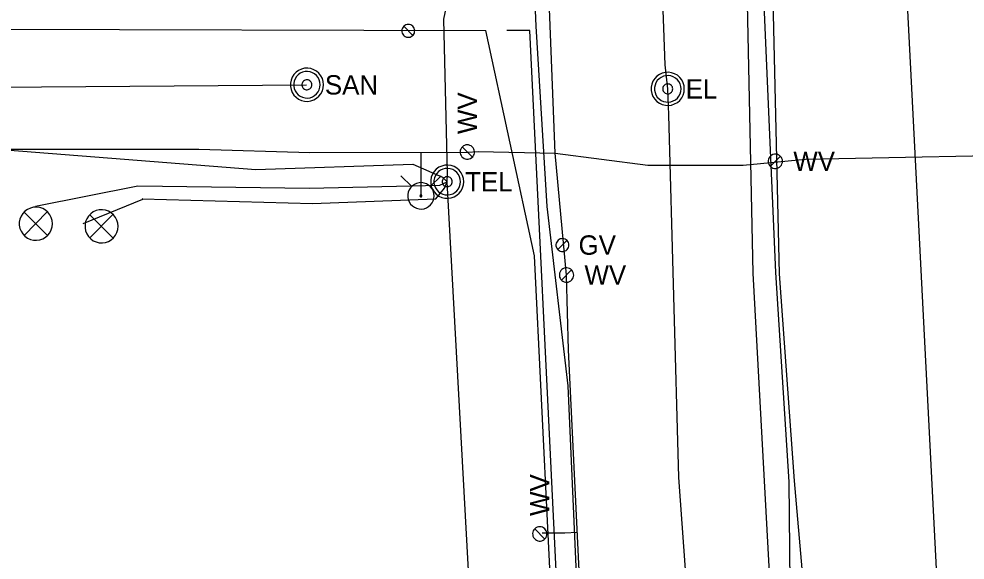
# Model space of a CAD drawing. Extents: x 600849 to 606371, y 330010 to 403088.
# Drawn here: x 604696 to 604884.2, y 334880.1 to 334987.6 of the extents above; entities that cross this region are included whole.
import ezdxf

# ---------------------------------------------------------------- set-up
doc = ezdxf.new("R2010")
doc.units = 0
for name, color, linetype in [('E_FTMS_Conduit', 7, 'Continuous'), ('E_LTG_CID', 7, 'Continuous'), ('E_SIG', 7, 'Continuous'), ('E_UTL_E', 7, 'Continuous'), ('E_UTL_E_UG', 7, 'Continuous'), ('E_UTL_FO_UG_QWEST', 7, 'Continuous'), ('E_UTL_G', 7, 'Continuous'), ('E_UTL_G_UG', 7, 'Continuous'), ('E_UTL_SAN', 7, 'Continuous'), ('E_UTL_SAN_UG', 7, 'Continuous'), ('E_UTL_SAN_UG_MMSD', 7, 'Continuous'), ('E_UTL_T_MH', 7, 'Continuous'), ('E_UTL_T_UG', 7, 'Continuous'), ('E_UTL_TV_UG', 7, 'Continuous'), ('E_UTL_W', 7, 'Continuous'), ('E_UTL_W_UG', 7, 'Continuous'), ('E_UTL_WHydrant', 7, 'Continuous')]:
    doc.layers.add(name, color=color, linetype=linetype)

msp = doc.modelspace()

# ---------------------------------------------------------------- linework, layer by layer
at = {"layer": 'E_FTMS_Conduit'}
msp.add_lwpolyline([(604865.66, 334623.82), (604860.3, 334662.92), (604859.68, 334742.73), (604857.4, 334780.45), (604853.68, 334856.29), (604850.24, 334895.79), (604847.27, 334936.94), (604845.54, 335011.51), (604843.22, 335054.36), (604842.26, 335092.55), (604835.93, 335170.05), (604833.24, 335224.35), (604834.53, 335254.76), (604831.45, 335295.34), (604820.14, 335431.05), (604817.01, 335471.26), (604813.1, 335515.04), (604806.53, 335560.93), (604800.96, 335611.56)], dxfattribs=at)
at = {"layer": 'E_LTG_CID'}
msp.add_lwpolyline([(604862.3, 334623.54), (604859.11, 334663.85), (604858.92, 334663.88), (604858.21, 334688.84), (604855.44, 334742.39), (604854.47, 334780.17), (604850.82, 334856.89), (604849.46, 334868.66), (604849.2, 334895.58), (604846.51, 334937.17), (604843.31, 335011.75), (604840.81, 335049.96), (604840.88, 335092.82), (604837.28, 335170.14), (604834.71, 335212.97)], dxfattribs=at)
at = {"layer": 'E_SIG'}
for points in [[(604702.69, 334946.9), (604702.63, 334947.52), (604702.46, 334948.12), (604702.17, 334948.68), (604701.78, 334949.17), (604701.31, 334949.58), (604700.76, 334949.9), (604700.17, 334950.1), (604699.55, 334950.19), (604698.92, 334950.16), (604698.31, 334950.01), (604697.74, 334949.75), (604697.23, 334949.39), (604696.8, 334948.94), (604696.46, 334948.41), (604696.23, 334947.83), (604696.11, 334947.21), (604696.11, 334946.58), (604696.23, 334945.97), (604696.46, 334945.38), (604696.8, 334944.86), (604697.23, 334944.4), (604697.74, 334944.04), (604698.31, 334943.78), (604698.92, 334943.63), (604699.55, 334943.6), (604700.17, 334943.69), (604700.76, 334943.89), (604701.31, 334944.21), (604701.78, 334944.62), (604702.17, 334945.11), (604702.46, 334945.67), (604702.63, 334946.27), (604702.69, 334946.9)], [(604701.66, 334949.23), (604697.05, 334944.57)], [(604697.05, 334949.18), (604701.7, 334944.53)], [(604715.77, 334946.38), (604715.71, 334947), (604715.53, 334947.61), (604715.25, 334948.16), (604714.86, 334948.66), (604714.38, 334949.07), (604713.84, 334949.38), (604713.25, 334949.59), (604712.63, 334949.68), (604712, 334949.65), (604711.39, 334949.5), (604710.82, 334949.24), (604710.31, 334948.87), (604709.88, 334948.42), (604709.54, 334947.89), (604709.3, 334947.31), (604709.19, 334946.69), (604709.19, 334946.07), (604709.3, 334945.45), (604709.54, 334944.87), (604709.88, 334944.34), (604710.31, 334943.89), (604710.82, 334943.52), (604711.39, 334943.26), (604712, 334943.11), (604712.63, 334943.08), (604713.25, 334943.17), (604713.84, 334943.38), (604714.38, 334943.69), (604714.86, 334944.1), (604715.25, 334944.6), (604715.53, 334945.15), (604715.71, 334945.76), (604715.77, 334946.38)], [(604714.73, 334948.71), (604710.12, 334944.06)], [(604710.12, 334948.67), (604714.78, 334944.01)]]:
    msp.add_lwpolyline(points, dxfattribs=at)
at = {"layer": 'E_UTL_E'}
for points in [[(604828.34, 334973.69), (604828.28, 334974.32), (604828.11, 334974.92), (604827.82, 334975.48), (604827.43, 334975.97), (604826.96, 334976.38), (604826.41, 334976.69), (604825.82, 334976.9), (604825.2, 334976.99), (604824.57, 334976.96), (604823.96, 334976.81), (604823.39, 334976.55), (604822.88, 334976.19), (604822.45, 334975.73), (604822.11, 334975.2), (604821.88, 334974.62), (604821.76, 334974), (604821.76, 334973.38), (604821.88, 334972.76), (604822.11, 334972.18), (604822.45, 334971.65), (604822.88, 334971.2), (604823.39, 334970.83), (604823.96, 334970.57), (604824.57, 334970.42), (604825.2, 334970.39), (604825.82, 334970.48), (604826.41, 334970.69), (604826.96, 334971), (604827.43, 334971.41), (604827.82, 334971.91), (604828.11, 334972.46), (604828.28, 334973.07), (604828.34, 334973.69)], [(604828.34, 334973.69), (604828.28, 334974.32), (604828.11, 334974.92), (604827.82, 334975.48), (604827.43, 334975.97), (604826.96, 334976.38), (604826.41, 334976.69), (604825.82, 334976.9), (604825.2, 334976.99), (604824.57, 334976.96), (604823.96, 334976.81), (604823.39, 334976.55), (604822.88, 334976.19), (604822.45, 334975.73), (604822.11, 334975.2), (604821.88, 334974.62), (604821.76, 334974), (604821.76, 334973.38), (604821.88, 334972.76), (604822.11, 334972.18), (604822.45, 334971.65), (604822.88, 334971.2), (604823.39, 334970.83), (604823.96, 334970.57), (604824.57, 334970.42), (604825.2, 334970.39), (604825.82, 334970.48), (604826.41, 334970.69), (604826.96, 334971), (604827.43, 334971.41), (604827.82, 334971.91), (604828.11, 334972.46), (604828.28, 334973.07), (604828.34, 334973.69)], [(604827.68, 334973.69), (604827.63, 334974.19), (604827.49, 334974.67), (604827.26, 334975.12), (604826.95, 334975.51), (604826.57, 334975.84), (604826.14, 334976.09), (604825.66, 334976.26), (604825.17, 334976.33), (604824.67, 334976.3), (604824.18, 334976.19), (604823.72, 334975.98), (604823.31, 334975.69), (604822.97, 334975.32), (604822.7, 334974.9), (604822.51, 334974.43), (604822.41, 334973.94), (604822.41, 334973.44), (604822.51, 334972.95), (604822.7, 334972.48), (604822.97, 334972.06), (604823.31, 334971.7), (604823.72, 334971.4), (604824.18, 334971.2), (604824.67, 334971.08), (604825.17, 334971.05), (604825.66, 334971.13), (604826.14, 334971.29), (604826.57, 334971.54), (604826.95, 334971.87), (604827.26, 334972.26), (604827.49, 334972.71), (604827.63, 334973.19), (604827.68, 334973.69)], [(604827.68, 334973.69), (604827.63, 334974.19), (604827.49, 334974.67), (604827.26, 334975.12), (604826.95, 334975.51), (604826.57, 334975.84), (604826.14, 334976.09), (604825.66, 334976.26), (604825.17, 334976.33), (604824.67, 334976.3), (604824.18, 334976.19), (604823.72, 334975.98), (604823.31, 334975.69), (604822.97, 334975.32), (604822.7, 334974.9), (604822.51, 334974.43), (604822.41, 334973.94), (604822.41, 334973.44), (604822.51, 334972.95), (604822.7, 334972.48), (604822.97, 334972.06), (604823.31, 334971.7), (604823.72, 334971.4), (604824.18, 334971.2), (604824.67, 334971.08), (604825.17, 334971.05), (604825.66, 334971.13), (604826.14, 334971.29), (604826.57, 334971.54), (604826.95, 334971.87), (604827.26, 334972.26), (604827.49, 334972.71), (604827.63, 334973.19), (604827.68, 334973.69)], [(604826.03, 334973.69), (604826.01, 334973.88), (604825.96, 334974.06), (604825.87, 334974.23), (604825.76, 334974.37), (604825.62, 334974.5), (604825.45, 334974.59), (604825.28, 334974.65), (604825.09, 334974.68), (604824.9, 334974.67), (604824.72, 334974.63), (604824.55, 334974.55), (604824.39, 334974.44), (604824.26, 334974.3), (604824.16, 334974.14), (604824.09, 334973.97), (604824.06, 334973.79), (604824.06, 334973.6), (604824.09, 334973.41), (604824.16, 334973.24), (604824.26, 334973.08), (604824.39, 334972.94), (604824.55, 334972.83), (604824.72, 334972.76), (604824.9, 334972.71), (604825.09, 334972.7), (604825.28, 334972.73), (604825.45, 334972.79), (604825.62, 334972.88), (604825.76, 334973.01), (604825.87, 334973.16), (604825.96, 334973.32), (604826.01, 334973.5), (604826.03, 334973.69)], [(604826.03, 334973.69), (604826.01, 334973.88), (604825.96, 334974.06), (604825.87, 334974.23), (604825.76, 334974.37), (604825.62, 334974.5), (604825.45, 334974.59), (604825.28, 334974.65), (604825.09, 334974.68), (604824.9, 334974.67), (604824.72, 334974.63), (604824.55, 334974.55), (604824.39, 334974.44), (604824.26, 334974.3), (604824.16, 334974.14), (604824.09, 334973.97), (604824.06, 334973.79), (604824.06, 334973.6), (604824.09, 334973.41), (604824.16, 334973.24), (604824.26, 334973.08), (604824.39, 334972.94), (604824.55, 334972.83), (604824.72, 334972.76), (604824.9, 334972.71), (604825.09, 334972.7), (604825.28, 334972.73), (604825.45, 334972.79), (604825.62, 334972.88), (604825.76, 334973.01), (604825.87, 334973.16), (604825.96, 334973.32), (604826.01, 334973.5), (604826.03, 334973.69)]]:
    msp.add_lwpolyline(points, dxfattribs=at)
at = {"layer": 'E_UTL_E_UG'}
msp.add_lwpolyline([(604841.27, 334614.96), (604838.91, 334672.58), (604835.72, 334731.86), (604833.33, 334793.2), (604830.28, 334854.41), (604827.22, 334896.47), (604825.25, 334968.56), (604825.04, 334973.69), (604824.51, 334978.47), (604823.31, 335011.26), (604820.86, 335070.81), (604819.86, 335112.84), (604819.04, 335158.63), (604817.07, 335191.32), (604814.49, 335235.91), (604811.85, 335279.29), (604809.46, 335325.61), (604807.12, 335373), (604804.05, 335421.46), (604799.37, 335470.45), (604793.24, 335522.54), (604789.06, 335554.45), (604783.73, 335590.4)], dxfattribs=at)
at = {"layer": 'E_UTL_FO_UG_QWEST'}
msp.add_lwpolyline([(604880.24, 334183.25), (604876.98, 334256.9), (604873.2, 334330.88), (604873.06, 334361.71), (604869.66, 334408.48), (604865.91, 334483.81), (604863.36, 334557.53), (604860.02, 334633.27), (604855.03, 334705.91), (604850.49, 334782.01), (604846.38, 334856.9), (604842.05, 334937.04), (604840.43, 335012.73), (604837.31, 335089.26), (604832.93, 335173.7), (604830.71, 335249.27), (604828.33, 335311.14), (604825.79, 335353.18), (604822.55, 335385.33), (604819.59, 335404.65), (604816.19, 335465.69), (604807.94, 335539.85), (604801.77, 335593.87)], dxfattribs=at)
at = {"layer": 'E_UTL_G'}
for points in [[(604773.45, 334986.49), (604773.21, 334986.47), (604772.97, 334986.4), (604772.76, 334986.29), (604772.56, 334986.14), (604772.41, 334985.95), (604772.28, 334985.74), (604772.2, 334985.51), (604772.17, 334985.27), (604772.18, 334985.03), (604772.24, 334984.79), (604772.34, 334984.57), (604772.48, 334984.37), (604772.66, 334984.2), (604772.86, 334984.07), (604773.09, 334983.98), (604773.33, 334983.93), (604773.57, 334983.93), (604773.81, 334983.98), (604774.04, 334984.07), (604774.24, 334984.2), (604774.42, 334984.37), (604774.56, 334984.57), (604774.66, 334984.79), (604774.72, 334985.03), (604774.73, 334985.27), (604774.7, 334985.51), (604774.62, 334985.74), (604774.5, 334985.95), (604774.34, 334986.14), (604774.14, 334986.29), (604773.93, 334986.4), (604773.69, 334986.47), (604773.45, 334986.49)], [(604774.36, 334984.3), (604772.54, 334986.12)], [(604805.38, 334942.65), (604805.36, 334942.89), (604805.29, 334943.13), (604805.18, 334943.34), (604805.03, 334943.54), (604804.84, 334943.7), (604804.63, 334943.82), (604804.4, 334943.9), (604804.16, 334943.93), (604803.92, 334943.92), (604803.68, 334943.86), (604803.46, 334943.76), (604803.26, 334943.62), (604803.09, 334943.44), (604802.96, 334943.24), (604802.87, 334943.01), (604802.82, 334942.77), (604802.82, 334942.53), (604802.87, 334942.29), (604802.96, 334942.06), (604803.09, 334941.86), (604803.26, 334941.68), (604803.46, 334941.54), (604803.68, 334941.44), (604803.92, 334941.38), (604804.16, 334941.37), (604804.4, 334941.4), (604804.63, 334941.48), (604804.84, 334941.6), (604805.03, 334941.76), (604805.18, 334941.96), (604805.29, 334942.17), (604805.36, 334942.41), (604805.38, 334942.65)], [(604803.19, 334941.74), (604805.01, 334943.56)]]:
    msp.add_lwpolyline(points, dxfattribs=at)
at = {"layer": 'E_UTL_G_UG'}
msp.add_line((604609.16, 334985.7), (604788.86, 334985.31), dxfattribs=at)
for points in [[(604813.42, 334699.61), (604806.93, 334770.39), (604798.55, 334940.51), (604788.86, 334985.31)], [(604812.28, 334776.17), (604807.85, 334775.95), (604797.65, 334985.29), (604793.02, 334985.3)], [(604812.28, 334776.17), (604807.85, 334775.95), (604797.65, 334985.29)]]:
    msp.add_lwpolyline(points, dxfattribs=at)
at = {"layer": 'E_UTL_SAN'}
for points in [[(604756.6, 334974.5), (604756.54, 334975.13), (604756.37, 334975.73), (604756.08, 334976.29), (604755.69, 334976.78), (604755.22, 334977.19), (604754.67, 334977.5), (604754.08, 334977.71), (604753.46, 334977.8), (604752.83, 334977.77), (604752.22, 334977.62), (604751.65, 334977.36), (604751.14, 334977), (604750.71, 334976.54), (604750.37, 334976.01), (604750.14, 334975.43), (604750.02, 334974.81), (604750.02, 334974.19), (604750.14, 334973.57), (604750.37, 334972.99), (604750.71, 334972.46), (604751.14, 334972.01), (604751.65, 334971.64), (604752.22, 334971.38), (604752.83, 334971.23), (604753.46, 334971.2), (604754.08, 334971.29), (604754.67, 334971.5), (604755.22, 334971.81), (604755.69, 334972.22), (604756.08, 334972.72), (604756.37, 334973.27), (604756.54, 334973.88), (604756.6, 334974.5)], [(604755.94, 334974.5), (604755.89, 334975), (604755.75, 334975.48), (604755.52, 334975.93), (604755.21, 334976.32), (604754.83, 334976.65), (604754.4, 334976.9), (604753.92, 334977.07), (604753.43, 334977.14), (604752.93, 334977.11), (604752.44, 334977), (604751.98, 334976.79), (604751.57, 334976.5), (604751.23, 334976.13), (604750.96, 334975.71), (604750.77, 334975.24), (604750.67, 334974.75), (604750.67, 334974.25), (604750.77, 334973.76), (604750.96, 334973.29), (604751.23, 334972.87), (604751.57, 334972.51), (604751.98, 334972.21), (604752.44, 334972.01), (604752.93, 334971.89), (604753.43, 334971.86), (604753.92, 334971.94), (604754.4, 334972.1), (604754.83, 334972.35), (604755.21, 334972.68), (604755.52, 334973.07), (604755.75, 334973.52), (604755.89, 334974), (604755.94, 334974.5)], [(604754.29, 334974.5), (604754.27, 334974.69), (604754.22, 334974.87), (604754.14, 334975.04), (604754.02, 334975.18), (604753.88, 334975.31), (604753.71, 334975.4), (604753.54, 334975.46), (604753.35, 334975.49), (604753.16, 334975.48), (604752.98, 334975.44), (604752.81, 334975.36), (604752.65, 334975.25), (604752.52, 334975.11), (604752.42, 334974.95), (604752.35, 334974.78), (604752.32, 334974.6), (604752.32, 334974.41), (604752.35, 334974.22), (604752.42, 334974.05), (604752.52, 334973.89), (604752.65, 334973.75), (604752.81, 334973.64), (604752.98, 334973.57), (604753.16, 334973.52), (604753.35, 334973.51), (604753.54, 334973.54), (604753.71, 334973.6), (604753.88, 334973.69), (604754.02, 334973.82), (604754.14, 334973.97), (604754.22, 334974.13), (604754.27, 334974.31), (604754.29, 334974.5)]]:
    msp.add_lwpolyline(points, dxfattribs=at)
at = {"layer": 'E_UTL_SAN_UG'}
msp.add_line((604610.8, 334973.38), (604753.19, 334974.49), dxfattribs=at)
at = {"layer": 'E_UTL_SAN_UG_MMSD'}
msp.add_line((604889.58, 334663.41), (604856.43, 335306.2), dxfattribs=at)
at = {"layer": 'E_UTL_T_MH'}
for points in [[(604784.49, 334955.24), (604784.43, 334955.87), (604784.26, 334956.47), (604783.97, 334957.03), (604783.58, 334957.52), (604783.11, 334957.93), (604782.56, 334958.24), (604781.97, 334958.45), (604781.35, 334958.54), (604780.72, 334958.51), (604780.11, 334958.36), (604779.54, 334958.1), (604779.03, 334957.74), (604778.6, 334957.28), (604778.26, 334956.75), (604778.03, 334956.17), (604777.91, 334955.55), (604777.91, 334954.93), (604778.03, 334954.31), (604778.26, 334953.73), (604778.6, 334953.2), (604779.03, 334952.75), (604779.54, 334952.38), (604780.11, 334952.12), (604780.72, 334951.97), (604781.35, 334951.94), (604781.97, 334952.03), (604782.56, 334952.24), (604783.11, 334952.55), (604783.58, 334952.96), (604783.97, 334953.46), (604784.26, 334954.01), (604784.43, 334954.62), (604784.49, 334955.24)], [(604783.83, 334955.24), (604783.78, 334955.74), (604783.64, 334956.22), (604783.41, 334956.67), (604783.1, 334957.06), (604782.72, 334957.39), (604782.29, 334957.64), (604781.81, 334957.81), (604781.32, 334957.88), (604780.82, 334957.85), (604780.33, 334957.74), (604779.87, 334957.53), (604779.46, 334957.24), (604779.12, 334956.87), (604778.85, 334956.45), (604778.66, 334955.99), (604778.56, 334955.49), (604778.56, 334954.99), (604778.66, 334954.5), (604778.85, 334954.03), (604779.12, 334953.61), (604779.46, 334953.25), (604779.87, 334952.95), (604780.33, 334952.75), (604780.82, 334952.63), (604781.32, 334952.6), (604781.81, 334952.68), (604782.29, 334952.84), (604782.72, 334953.09), (604783.1, 334953.42), (604783.41, 334953.81), (604783.64, 334954.26), (604783.78, 334954.74), (604783.83, 334955.24)], [(604782.18, 334955.24), (604782.16, 334955.43), (604782.11, 334955.61), (604782.02, 334955.78), (604781.91, 334955.92), (604781.77, 334956.05), (604781.6, 334956.14), (604781.43, 334956.2), (604781.24, 334956.23), (604781.05, 334956.22), (604780.87, 334956.18), (604780.7, 334956.1), (604780.54, 334955.99), (604780.41, 334955.85), (604780.31, 334955.69), (604780.24, 334955.52), (604780.21, 334955.34), (604780.21, 334955.15), (604780.24, 334954.96), (604780.31, 334954.79), (604780.41, 334954.63), (604780.54, 334954.49), (604780.7, 334954.38), (604780.87, 334954.31), (604781.05, 334954.26), (604781.24, 334954.25), (604781.43, 334954.28), (604781.6, 334954.34), (604781.77, 334954.43), (604781.91, 334954.56), (604782.02, 334954.71), (604782.11, 334954.87), (604782.16, 334955.05), (604782.18, 334955.24)]]:
    msp.add_lwpolyline(points, dxfattribs=at)
at = {"layer": 'E_UTL_T_UG'}
for points in [[(604781.19, 334955.24), (604781.26, 334956.9), (604780.52, 334987.51), (604781.76, 334993.48), (604785.16, 334996.51), (604790.1, 334997.63), (604799.35, 335001.31), (604800.8, 335015.92), (604798.74, 335053.44), (604796.57, 335107.86), (604795.96, 335122.04), (604795.68, 335136.2), (604794.7, 335159.47), (604786.68, 335164.8)], [(604589.13, 334957.04), (604623.62, 334957.99), (604662.26, 334958.5), (604693.45, 334961.55), (604743.11, 334957.64), (604774.39, 334958.71), (604780.28, 334956.17), (604781.19, 334955.24)], [(604699.31, 334950.36), (604719.65, 334954.43), (604753.79, 334953.96), (604779.76, 334954.58), (604781.19, 334955.24)], [(604708.84, 334946.91), (604720.69, 334951.77), (604720.57, 334951.85), (604754.39, 334950.91), (604778.96, 334951.84), (604780.66, 334953.95), (604781.19, 334955.24)], [(604800.46, 334604.09), (604781.19, 334955.24)]]:
    msp.add_lwpolyline(points, dxfattribs=at)
at = {"layer": 'E_UTL_TV_UG'}
msp.add_lwpolyline([(604817.34, 334644.42), (604816.08, 334676.3), (604813.81, 334728.2), (604809.39, 334794.06), (604807.73, 334857.81), (604805.23, 334914.65), (604801.05, 334950.32), (604798.9, 334986.15), (604797.61, 335015.7), (604796.88, 335045.48), (604794.41, 335107.34), (604793.45, 335122.45), (604792.96, 335142.41), (604790.74, 335160.15), (604782.82, 335165.57)], dxfattribs=at)
at = {"layer": 'E_UTL_W'}
for points in [[(604785.19, 334962.57), (604784.92, 334962.54), (604784.66, 334962.46), (604784.42, 334962.34), (604784.21, 334962.17), (604784.03, 334961.97), (604783.89, 334961.73), (604783.8, 334961.48), (604783.77, 334961.21), (604783.78, 334960.94), (604783.84, 334960.67), (604783.96, 334960.43), (604784.11, 334960.21), (604784.31, 334960.02), (604784.54, 334959.87), (604784.79, 334959.77), (604785.05, 334959.72), (604785.33, 334959.72), (604785.59, 334959.77), (604785.84, 334959.87), (604786.07, 334960.02), (604786.27, 334960.21), (604786.43, 334960.43), (604786.54, 334960.67), (604786.6, 334960.94), (604786.61, 334961.21), (604786.58, 334961.48), (604786.49, 334961.73), (604786.35, 334961.97), (604786.17, 334962.17), (604785.96, 334962.34), (604785.72, 334962.46), (604785.46, 334962.54), (604785.19, 334962.57)], [(604786.2, 334960.13), (604784.18, 334962.15)], [(604847.87, 334959.3), (604847.84, 334959.57), (604847.76, 334959.83), (604847.64, 334960.07), (604847.47, 334960.28), (604847.27, 334960.46), (604847.03, 334960.6), (604846.78, 334960.69), (604846.51, 334960.72), (604846.24, 334960.71), (604845.97, 334960.65), (604845.73, 334960.54), (604845.51, 334960.38), (604845.32, 334960.18), (604845.17, 334959.95), (604845.07, 334959.7), (604845.02, 334959.44), (604845.02, 334959.16), (604845.07, 334958.9), (604845.17, 334958.65), (604845.32, 334958.42), (604845.51, 334958.22), (604845.73, 334958.07), (604845.97, 334957.95), (604846.24, 334957.89), (604846.51, 334957.88), (604846.78, 334957.91), (604847.03, 334958), (604847.27, 334958.14), (604847.47, 334958.32), (604847.64, 334958.53), (604847.76, 334958.77), (604847.84, 334959.03), (604847.87, 334959.3)], [(604845.43, 334958.29), (604847.45, 334960.31)], [(604806.35, 334936.69), (604806.32, 334936.96), (604806.24, 334937.22), (604806.12, 334937.46), (604805.95, 334937.67), (604805.75, 334937.85), (604805.51, 334937.99), (604805.26, 334938.08), (604804.99, 334938.11), (604804.72, 334938.1), (604804.45, 334938.04), (604804.21, 334937.93), (604803.99, 334937.77), (604803.8, 334937.57), (604803.65, 334937.34), (604803.55, 334937.09), (604803.5, 334936.83), (604803.5, 334936.55), (604803.55, 334936.29), (604803.65, 334936.04), (604803.8, 334935.81), (604803.99, 334935.61), (604804.21, 334935.46), (604804.45, 334935.34), (604804.72, 334935.28), (604804.99, 334935.27), (604805.26, 334935.3), (604805.51, 334935.39), (604805.75, 334935.53), (604805.95, 334935.71), (604806.12, 334935.92), (604806.24, 334936.16), (604806.32, 334936.42), (604806.35, 334936.69)], [(604803.91, 334935.68), (604805.93, 334937.7)], [(604799.6, 334886.68), (604799.33, 334886.65), (604799.07, 334886.57), (604798.83, 334886.45), (604798.62, 334886.28), (604798.44, 334886.08), (604798.3, 334885.84), (604798.21, 334885.59), (604798.18, 334885.32), (604798.19, 334885.05), (604798.25, 334884.78), (604798.37, 334884.54), (604798.52, 334884.32), (604798.72, 334884.13), (604798.95, 334883.98), (604799.2, 334883.88), (604799.46, 334883.83), (604799.74, 334883.83), (604800, 334883.88), (604800.25, 334883.98), (604800.48, 334884.13), (604800.68, 334884.32), (604800.84, 334884.54), (604800.95, 334884.78), (604801.01, 334885.05), (604801.02, 334885.32), (604800.99, 334885.59), (604800.9, 334885.84), (604800.76, 334886.08), (604800.58, 334886.28), (604800.37, 334886.45), (604800.13, 334886.57), (604799.87, 334886.65), (604799.6, 334886.68)], [(604800.61, 334884.24), (604798.59, 334886.26)]]:
    msp.add_lwpolyline(points, dxfattribs=at)
at = {"layer": 'E_UTL_W_UG'}
msp.add_line((604775.96, 334961.11), (604775.98, 334952.43), dxfattribs=at)
for points in [[(604846.62, 333845.73), (604845.91, 333962.63), (604845.14, 333993.13), (604845.77, 334042.88), (604845.13, 334077.17), (604842.87, 334162.23), (604837.44, 334211.69), (604837.01, 334265.02), (604832.72, 334352.02), (604829.86, 334407.8), (604827.89, 334453.7), (604825.43, 334498.81), (604822.75, 334554.4), (604821.56, 334581.06), (604817.29, 334667.8), (604815.06, 334708.63), (604813.04, 334742.82), (604812.12, 334767.3), (604810.04, 334815.66), (604808.35, 334858.79), (604805.32, 334921.82), (604804.92, 334936.69), (604802.65, 334960.89), (604797.31, 335097.75)], [(604592.01, 334961.73), (604731.8, 334961.73), (604753.88, 334961.04), (604785.19, 334961.14)], [(604785.19, 334961.14), (604787.35, 334961.22), (604802.65, 334960.89), (604821.06, 334958.55), (604840.06, 334958.51), (604852.44, 334959.69)], [(604852.44, 334959.69), (605011.72, 334962.88)], [(604807.06, 334885.55), (604804.56, 334885.43), (604800.06, 334885.42)]]:
    msp.add_lwpolyline(points, dxfattribs=at)
at = {"layer": 'E_UTL_WHydrant'}
for points in [[(604774.15, 334954.27), (604772, 334956.41)], [(604777.82, 334954.27), (604779.96, 334956.41)], [(604778.6, 334952.43), (604778.56, 334952.93), (604778.42, 334953.41), (604778.19, 334953.85), (604777.88, 334954.24), (604777.5, 334954.57), (604777.07, 334954.82), (604776.6, 334954.98), (604776.11, 334955.05), (604775.61, 334955.03), (604775.12, 334954.91), (604774.67, 334954.7), (604774.26, 334954.41), (604773.92, 334954.05), (604773.65, 334953.63), (604773.46, 334953.17), (604773.37, 334952.68), (604773.37, 334952.18), (604773.46, 334951.69), (604773.65, 334951.23), (604773.92, 334950.81), (604774.26, 334950.45), (604774.67, 334950.16), (604775.12, 334949.95), (604775.61, 334949.83), (604776.11, 334949.81), (604776.6, 334949.88), (604777.07, 334950.04), (604777.5, 334950.29), (604777.88, 334950.62), (604778.19, 334951.01), (604778.42, 334951.46), (604778.56, 334951.93), (604778.6, 334952.43)], [(604776.18, 334952.43), (604776.18, 334952.47), (604776.17, 334952.5), (604776.15, 334952.54), (604776.13, 334952.57), (604776.1, 334952.59), (604776.06, 334952.61), (604776.03, 334952.63), (604775.99, 334952.63), (604775.95, 334952.63), (604775.91, 334952.62), (604775.88, 334952.6), (604775.85, 334952.58), (604775.82, 334952.55), (604775.8, 334952.52), (604775.79, 334952.49), (604775.78, 334952.45), (604775.78, 334952.41), (604775.79, 334952.37), (604775.8, 334952.34), (604775.82, 334952.31), (604775.85, 334952.28), (604775.88, 334952.26), (604775.91, 334952.24), (604775.95, 334952.23), (604775.99, 334952.23), (604776.03, 334952.24), (604776.06, 334952.25), (604776.1, 334952.27), (604776.13, 334952.29), (604776.15, 334952.32), (604776.17, 334952.36), (604776.18, 334952.39), (604776.18, 334952.43)]]:
    msp.add_lwpolyline(points, dxfattribs=at)

# ---------------------------------------------------------------- texts
at = {"layer": 'E_UTL_E'}
msp.add_text('EL', height=3.849, dxfattribs=at).set_placement((604828.61, 334971.75))
msp.add_text('EL', height=3.849, dxfattribs=at).set_placement((604828.61, 334971.75))
at = {"layer": 'E_UTL_G'}
msp.add_text('GV', height=3.85, dxfattribs=at).set_placement((604807.31, 334940.73))
at = {"layer": 'E_UTL_SAN'}
msp.add_text('SAN', height=3.849, dxfattribs=at).set_placement((604756.87, 334972.56))
at = {"layer": 'E_UTL_T_MH'}
msp.add_text('TEL', height=3.849, dxfattribs=at).set_placement((604784.76, 334953.3))
at = {"layer": 'E_UTL_W'}
for p in [(604787.12, 334964.7), (604801.53, 334888.82)]:
    msp.add_text('WV', height=3.85, rotation=90, dxfattribs=at).set_placement(p)
for p in [(604850.01, 334957.38), (604808.49, 334934.77)]:
    msp.add_text('WV', height=3.85, dxfattribs=at).set_placement(p)

doc.saveas('drawing.dxf')
